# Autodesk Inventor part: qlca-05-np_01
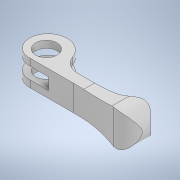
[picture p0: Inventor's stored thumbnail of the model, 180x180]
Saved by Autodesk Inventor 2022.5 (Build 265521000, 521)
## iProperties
Created: 2023-06
Part Number: qlca-05-np_01
Material: Generic
Document SubType Name: Modeling
Designer: ImaoCorp
Density: 1 g/cm^3
Appearance: Default
Author: ImaoCorp
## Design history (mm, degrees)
feature "qlca-05-np_01"
node "ソリッド1"
